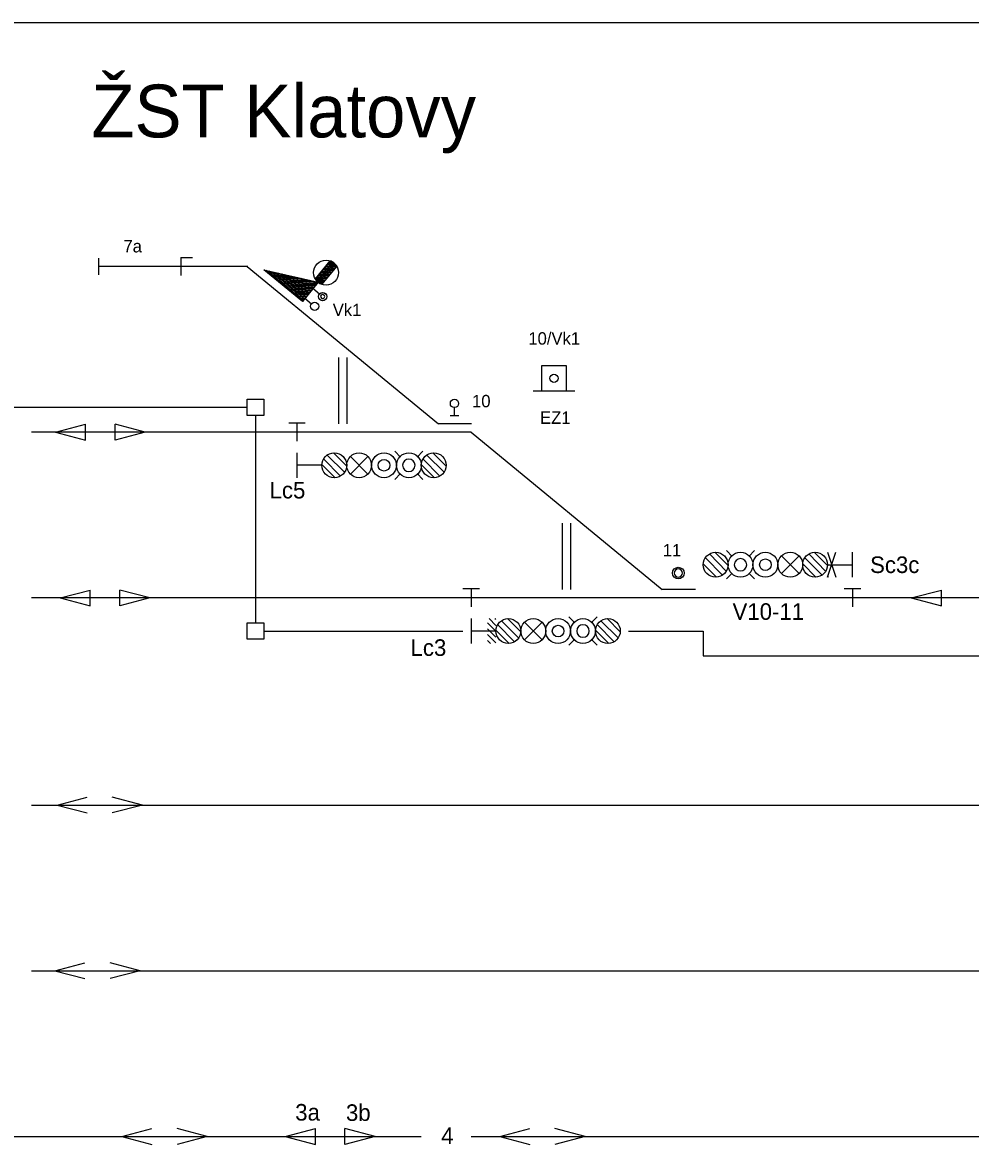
# Model space of a CAD drawing. Extents: x -1146 to 534, y 4 to 301.
# Drawn here: x -299.1 to -184.8, y 166 to 301.4 of the extents above; entities that cross this region are included whole.
import ezdxf

# ---------------------------------------------------------------- set-up
doc = ezdxf.new("R2010")
doc.units = 0
for name, color, linetype in [('1', 7, 'Continuous'), ('formát tisku', 7, 'Continuous'), ('kabel', 7, 'Continuous'), ('koleje', 7, 'Continuous'), ('návěstidla', 7, 'Continuous'), ('popisy', 7, 'Continuous'), ('čd', 7, 'Continuous')]:
    doc.layers.add(name, color=color, linetype=linetype)

# ---------------------------------------------------------------- blocks, each defined once
blk = doc.blocks.new('SB4')
for q in [(-1.39, 1.08), (0, -1.08)]:
    blk.add_line((0, 1.08), q)
blk = doc.blocks.new('NS16')
for p, q in [((-1.499, 0.6437), (-1.1298, 1.0129)), ((-1.4356, 0), (-0.4227, 1.0129)), ((-0.7285, 0), (0.2844, 1.0129)), ((-0.0214, 0), (0.9915, 1.0129)), ((0.6857, 0), (1.499, 0.8133)), ((1.3928, 0), (1.499, 0.1062))]:
    blk.add_line(p, q)
blk = doc.blocks.new('SB1')
for p, q in [((0, 1.08), (-1, 1.08)), ((1, 1.08), (0, 1.08)), ((0, 1.08), (0, -1.08))]:
    blk.add_line(p, q)
blk = doc.blocks.new('PZ2')
for start, end in [(0, 180), (180, 0)]:
    blk.add_arc((0, 2), 0.5, start, end)
blk = doc.blocks.new('PZ9')
for p, q in [((0, 1), (0, 1.97)), ((-0.53, 1), (0.53, 1))]:
    blk.add_line(p, q)
blk.add_circle((0, 2.47), 0.5)
blk = doc.blocks.new('_X32')
for p, q in [((-4.29, 1.02), (-2.58, 2.72)), ((-4.11, 1.02), (-2.23, 2.9)), ((-3.93, 1.02), (-1.87, 3.08)), ((-3.76, 1.02), (-1.52, 3.25)), ((-3.58, 1.02), (-1.16, 3.43)), ((-3.4, 1.02), (-0.81, 3.61)), ((-3.23, 1.02), (-0.46, 3.79)), ((-3.05, 1.02), (-0.1, 3.96)), ((-2.87, 1.02), (0.01, 3.89)), ((-2.7, 1.02), (0.01, 3.72)), ((-2.52, 1.02), (0.01, 3.54)), ((-2.34, 1.02), (0.01, 3.36)), ((-2.17, 1.02), (0.01, 3.19)), ((-1.99, 1.02), (0.01, 3.01)), ((-1.81, 1.02), (0.01, 2.83)), ((-5.52, 1.02), (-5.05, 1.49)), ((-5.35, 1.02), (-4.7, 1.66)), ((-5.17, 1.02), (-4.35, 1.84)), ((-4.99, 1.02), (-3.99, 2.02)), ((-4.82, 1.02), (-3.64, 2.19)), ((-4.64, 1.02), (-3.29, 2.37)), ((-4.46, 1.02), (-2.93, 2.55)), ((-1.64, 1.02), (0.01, 2.66)), ((-1.46, 1.02), (0.01, 2.48)), ((-1.28, 1.02), (0.01, 2.3)), ((-1.11, 1.02), (0.01, 2.13)), ((-0.93, 1.02), (0.01, 1.95)), ((-0.75, 1.02), (0.01, 1.77)), ((-0.57, 1.02), (0.01, 1.6)), ((-0.4, 1.02), (0.01, 1.42)), ((-5.88, 1.02), (-5.76, 1.13)), ((-5.7, 1.02), (-5.41, 1.31)), ((-0.22, 1.02), (0.01, 1.24)), ((-0.04, 1.02), (0.01, 1.07))]:
    blk.add_line(p, q)
blk = doc.blocks.new('VU24')
blk.add_lwpolyline([(0.01, 4.02), (0.01, 1.02), (-6, 1.02)], close=True)
for start, end in [(0, 180), (180, 0)]:
    blk.add_arc((1.53, 3.02), 0.25, start, end)
at = {"layer": '1'}
for p, q in [((1.03, 3.01), (0, 3.01)), ((-0.02, 1.49), (1.03, 1.49))]:
    blk.add_line(p, q, dxfattribs=at)
blk.add_lwpolyline([(0.01, 1.02), (-6, 1.02), (0.01, 4.02)], close=True, dxfattribs=at)
for centre in [(1.53, 3.02), (1.53, 1.5)]:
    blk.add_circle(centre, 0.5, dxfattribs=at)
blk.add_blockref('_X32', (0, 0))
blk = doc.blocks.new('_X30')
for p, q in [((-0.5, 0.47), (0.44, 1.41)), ((-0.5, 0.65), (0.26, 1.41)), ((-0.5, 0.83), (0.09, 1.41)), ((-0.5, 1.01), (-0.09, 1.41)), ((-0.5, 1.18), (-0.27, 1.41)), ((-0.5, 1.36), (-0.44, 1.41)), ((-0.5, 0.3), (0.5, 1.3)), ((-0.5, 0.12), (0.5, 1.12)), ((-0.5, -0.06), (0.5, 0.94)), ((-0.5, -0.23), (0.5, 0.77)), ((-0.5, -0.41), (0.5, 0.59)), ((-0.5, -0.59), (0.5, 0.41)), ((-0.5, -0.76), (0.5, 0.24)), ((-0.5, -0.94), (0.5, 0.06)), ((-0.5, -1.12), (0.5, -0.12)), ((-0.5, -1.29), (0.5, -0.29)), ((-0.44, -1.41), (0.5, -0.47)), ((-0.27, -1.41), (0.5, -0.65)), ((-0.09, -1.41), (0.5, -0.82)), ((0.09, -1.41), (0.5, -1)), ((0.26, -1.41), (0.5, -1.18)), ((0.44, -1.41), (0.5, -1.35))]:
    blk.add_line(p, q)
blk = doc.blocks.new('VU9')
for p, q in [((-0.5, 2.91), (-0.5, 0.09)), ((0, 3), (0, 0)), ((0, 2.91), (0, 0.09)), ((0.5, 2.91), (0.5, 0.09))]:
    blk.add_line(p, q)
blk.add_lwpolyline([(-0.5, 2.91), (0.5, 2.91), (0.5, 0.09), (-0.5, 0.09), (-0.5, 2.91)])
blk.add_circle((0, 1.5), 1.5)
for radius, start, end in [(1.5, 70.5288, 109.4712), (1.25, 70.5288, 109.4712), (1.5, 250.5288, 289.4712), (1.25, 250.5288, 289.4712)]:
    blk.add_arc((0, 1.5), radius, start, end)
blk.add_blockref('_X30', (0, 1.5))
blk = doc.blocks.new('PZ14')
for p, q in [((1.5, 3), (-1.5, 3)), ((-1.5, 3), (-1.5, 0)), ((1.5, 0), (1.5, 3)), ((-2.5, 0), (2.5, 0)), ((-1.5, 0), (1.5, 0))]:
    blk.add_line(p, q)
blk.add_circle((0, 1.5), 0.5)

msp = doc.modelspace()

# ---------------------------------------------------------------- linework, layer by layer
for p, q in [((-295.14, 252), (-291.51, 252.95)), ((-295.14, 252), (-291.51, 251.05)), ((-284.3, 252), (-287.94, 252.95)), ((-284.3, 252), (-287.94, 251.05)), ((-266, 249.5), (-266, 246.5)), ((-260.3, 247.2), (-262.3, 249.2)), ((-260, 247.9), (-261.6, 249.5)), ((-253.5, 249), (-254.2, 249.7)), ((-251.5, 249), (-250.8, 249.7)), ((-248.3, 247.2), (-250.3, 249.2)), ((-248, 247.9), (-249.6, 249.5)), ((-263, 248), (-266, 248)), ((-261.4, 246.5), (-263, 248.1)), ((-260.75, 246.7), (-262.8, 248.8)), ((-249.4, 246.5), (-251, 248.1)), ((-248.75, 246.7), (-250.8, 248.8)), ((-253.5, 247), (-254.2, 246.3)), ((-251.5, 247), (-250.8, 246.3)), ((-216.25, 237.3), (-214.2, 235.2)), ((-215.6, 237.5), (-214, 235.9)), ((-213.5, 237), (-214.2, 237.7)), ((-211.5, 237), (-210.8, 237.7)), ((-204.25, 237.3), (-202.2, 235.2)), ((-203.6, 237.5), (-202, 235.9)), ((-199, 234.5), (-199, 237.5)), ((-217, 236.1), (-215.4, 234.5)), ((-216.7, 236.8), (-214.7, 234.8)), ((-205, 236.1), (-203.4, 234.5)), ((-204.7, 236.8), (-202.7, 234.8)), ((-202, 236), (-199, 236)), ((-213.5, 235), (-214.2, 234.3)), ((-211.5, 235), (-210.8, 234.3)), ((-202, 234.61), (-201.89, 234.5)), ((-294.58, 232), (-290.94, 232.95)), ((-283.74, 232), (-287.38, 232.95)), ((-191.9, 232), (-188.27, 232.95)), ((-294.58, 232), (-290.94, 231.05)), ((-283.74, 232), (-287.38, 231.05)), ((-191.9, 232), (-188.27, 231.05)), ((-245, 229.5), (-245, 226.5)), ((-239.3, 227.2), (-241.3, 229.2)), ((-239, 227.9), (-240.6, 229.5)), ((-232.5, 229), (-233.2, 229.7)), ((-230.5, 229), (-229.8, 229.7)), ((-227.3, 227.2), (-229.3, 229.2)), ((-227, 227.9), (-228.6, 229.5)), ((-242, 228), (-245, 228)), ((-240.4, 226.5), (-242, 228.1)), ((-239.75, 226.7), (-241.8, 228.8)), ((-228.4, 226.5), (-230, 228.1)), ((-227.75, 226.7), (-229.8, 228.8)), ((-232.5, 227), (-233.2, 226.3)), ((-230.5, 227), (-229.8, 226.3)), ((-294.94, 207), (-291.31, 207.95)), ((-284.64, 207), (-288.27, 207.95)), ((-294.94, 207), (-291.31, 206.05)), ((-284.64, 207), (-288.27, 206.05)), ((-295.21, 187), (-291.58, 187.95)), ((-295.21, 187), (-291.58, 186.05)), ((-284.91, 187), (-288.55, 187.95)), ((-284.91, 187), (-288.55, 186.05)), ((-287.13, 167), (-283.5, 167.95)), ((-276.83, 167), (-280.46, 167.95)), ((-267.41, 167), (-263.77, 167.95)), ((-256.57, 167), (-260.21, 167.95)), ((-241.54, 167), (-237.91, 167.95)), ((-231.24, 167), (-234.88, 167.95)), ((-287.13, 167), (-283.5, 166.05)), ((-276.83, 167), (-280.46, 166.05)), ((-267.41, 167), (-263.77, 166.05)), ((-256.57, 167), (-260.21, 166.05)), ((-241.54, 167), (-237.91, 166.05)), ((-231.24, 167), (-234.88, 166.05))]:
    msp.add_line(p, q)
for centre, radius in [((-262.9, 268.36), 0.5), ((-261.5, 248), 1.5), ((-258.5, 248), 1.5), ((-255.5, 248), 1.5), ((-252.5, 248), 1.5), ((-249.5, 248), 1.5), ((-255.5, 248), 0.7), ((-215.5, 236), 1.5), ((-212.5, 236), 1.5), ((-209.5, 236), 1.5), ((-206.5, 236), 1.5), ((-203.5, 236), 1.5), ((-220, 235), 0.7), ((-209.5, 236), 0.7), ((-240.5, 228), 1.5), ((-237.5, 228), 1.5), ((-234.5, 228), 1.5), ((-231.5, 228), 1.5), ((-228.5, 228), 1.5), ((-234.5, 228), 0.7)]:
    msp.add_circle(centre, radius)
for centre, start, end in [((-252.5, 248), 90, 270), ((-252.5, 248), 270, 90), ((-212.5, 236), 90, 270), ((-212.5, 236), 270, 90), ((-231.5, 228), 90, 270), ((-231.5, 228), 270, 90)]:
    msp.add_arc(centre, 0.75, start, end)
at = {"layer": 'formát tisku'}
msp.add_lwpolyline([(-305.96, 301.44), (-95.96, 301.44), (-95.96, 4.44), (-305.96, 4.44)], close=True, dxfattribs=at)
at = {"layer": 'kabel'}
for p, q in [((-338, 255), (-272, 255)), ((-271, 254), (-271, 229)), ((-270, 228), (-246, 228))]:
    msp.add_line(p, q, dxfattribs=at)
for points in [[(-272, 256), (-270, 256), (-270, 254), (-272, 254)], [(-272, 229), (-270, 229), (-270, 227), (-272, 227)]]:
    msp.add_lwpolyline(points, close=True, dxfattribs=at)
msp.add_lwpolyline([(-226, 228), (-217, 228), (-217, 225), (-165, 225)], dxfattribs=at)
at = {"layer": 'koleje'}
for p, q in [((-289.93, 273), (-289.93, 271)), ((-271.93, 272), (-289.93, 272)), ((-272, 272), (-248.93, 253)), ((-261, 261), (-261, 253)), ((-260, 261), (-260, 253)), ((-245, 252), (-298, 252)), ((-244.93, 253), (-248.93, 253)), ((-245, 252), (-221.93, 233)), ((-234, 241), (-234, 233)), ((-233, 241), (-233, 233)), ((-217.93, 233), (-221.93, 233)), ((-175.87, 232), (-298, 232)), ((-298, 207), (-135, 207)), ((-298, 187), (-160, 187)), ((-360, 167), (-251, 167)), ((-245, 167), (-164, 167))]:
    msp.add_line(p, q, dxfattribs=at)
at = {"layer": 'návěstidla'}
for p, q in [((-259.56, 249.06), (-257.44, 246.94)), ((-259.56, 246.94), (-257.44, 249.06)), ((-205.44, 234.94), (-207.56, 237.06)), ((-205.44, 237.06), (-207.56, 234.94)), ((-238.56, 229.06), (-236.44, 226.94)), ((-238.56, 226.94), (-236.44, 229.06))]:
    msp.add_line(p, q, dxfattribs=at)
at = {"layer": 'čd'}
for p, q in [((-291.51, 251.05), (-291.51, 252.95)), ((-287.94, 251.05), (-287.94, 252.95)), ((-202, 237.5), (-200.99, 234.51)), ((-201.99, 234.51), (-200.99, 237.51)), ((-290.94, 231.05), (-290.94, 232.95)), ((-287.38, 231.05), (-287.38, 232.95)), ((-188.27, 231.05), (-188.27, 232.95)), ((-263.77, 166.05), (-263.77, 167.95)), ((-260.21, 166.05), (-260.21, 167.95))]:
    msp.add_line(p, q, dxfattribs=at)

# ---------------------------------------------------------------- block references
at = {"layer": 'návěstidla', "rotation": 90}
msp.add_blockref('NS16', (-242, 228), dxfattribs=at)
at = {"layer": 'čd', "rotation": -39.472459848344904}
for name, p in [('VU24', (-266, 267)), ('VU9', (-263.44, 270.1))]:
    msp.add_blockref(name, p, dxfattribs=at)
at = {"layer": 'čd', "yscale": -1, "rotation": 180}
msp.add_blockref('SB4', (-280, 272), dxfattribs=at)
at = {"layer": 'čd'}
for name, p in [('PZ14', (-235, 257)), ('PZ9', (-247, 253)), ('SB1', (-266, 252)), ('PZ2', (-220, 233)), ('PZ2', (-220, 233)), ('SB1', (-245, 232)), ('SB1', (-199, 232))]:
    msp.add_blockref(name, p, dxfattribs=at)

# ---------------------------------------------------------------- texts
for s, p in [('7a', (-286.93, 273.69)), ('Vk1', (-261.68, 266)), ('10/Vk1', (-238.09, 262.56)), ('10', (-244.88, 255)), ('EZ1', (-236.68, 253)), ('11', (-221.88, 237))]:
    msp.add_text(s, height=1.5).set_placement(p)
at = {"layer": 'popisy'}
for s, height, p in [('ŽST Klatovy', 6.3738, (-290.81, 287.57)), ('Lc5', 2, (-269.3, 244)), ('Sc3c', 2, (-196.87, 235)), ('V10-11', 2, (-213.46, 229.35)), ('Lc3', 2, (-252.3, 225)), ('3a', 2, (-266.21, 168.92)), ('3b', 2, (-260.09, 168.88)), ('4', 2, (-248.6, 166.1))]:
    msp.add_text(s, height=height, dxfattribs=at).set_placement(p)

doc.saveas('drawing.dxf')
